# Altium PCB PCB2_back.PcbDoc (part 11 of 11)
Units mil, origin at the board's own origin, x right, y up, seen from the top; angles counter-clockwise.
Board outline 6299 x 3937 mil, 4 copper layers (TopLayer, GROUND, VCC, BottomLayer); 290 components, 470 nets, 2252 pads, 825 vias.
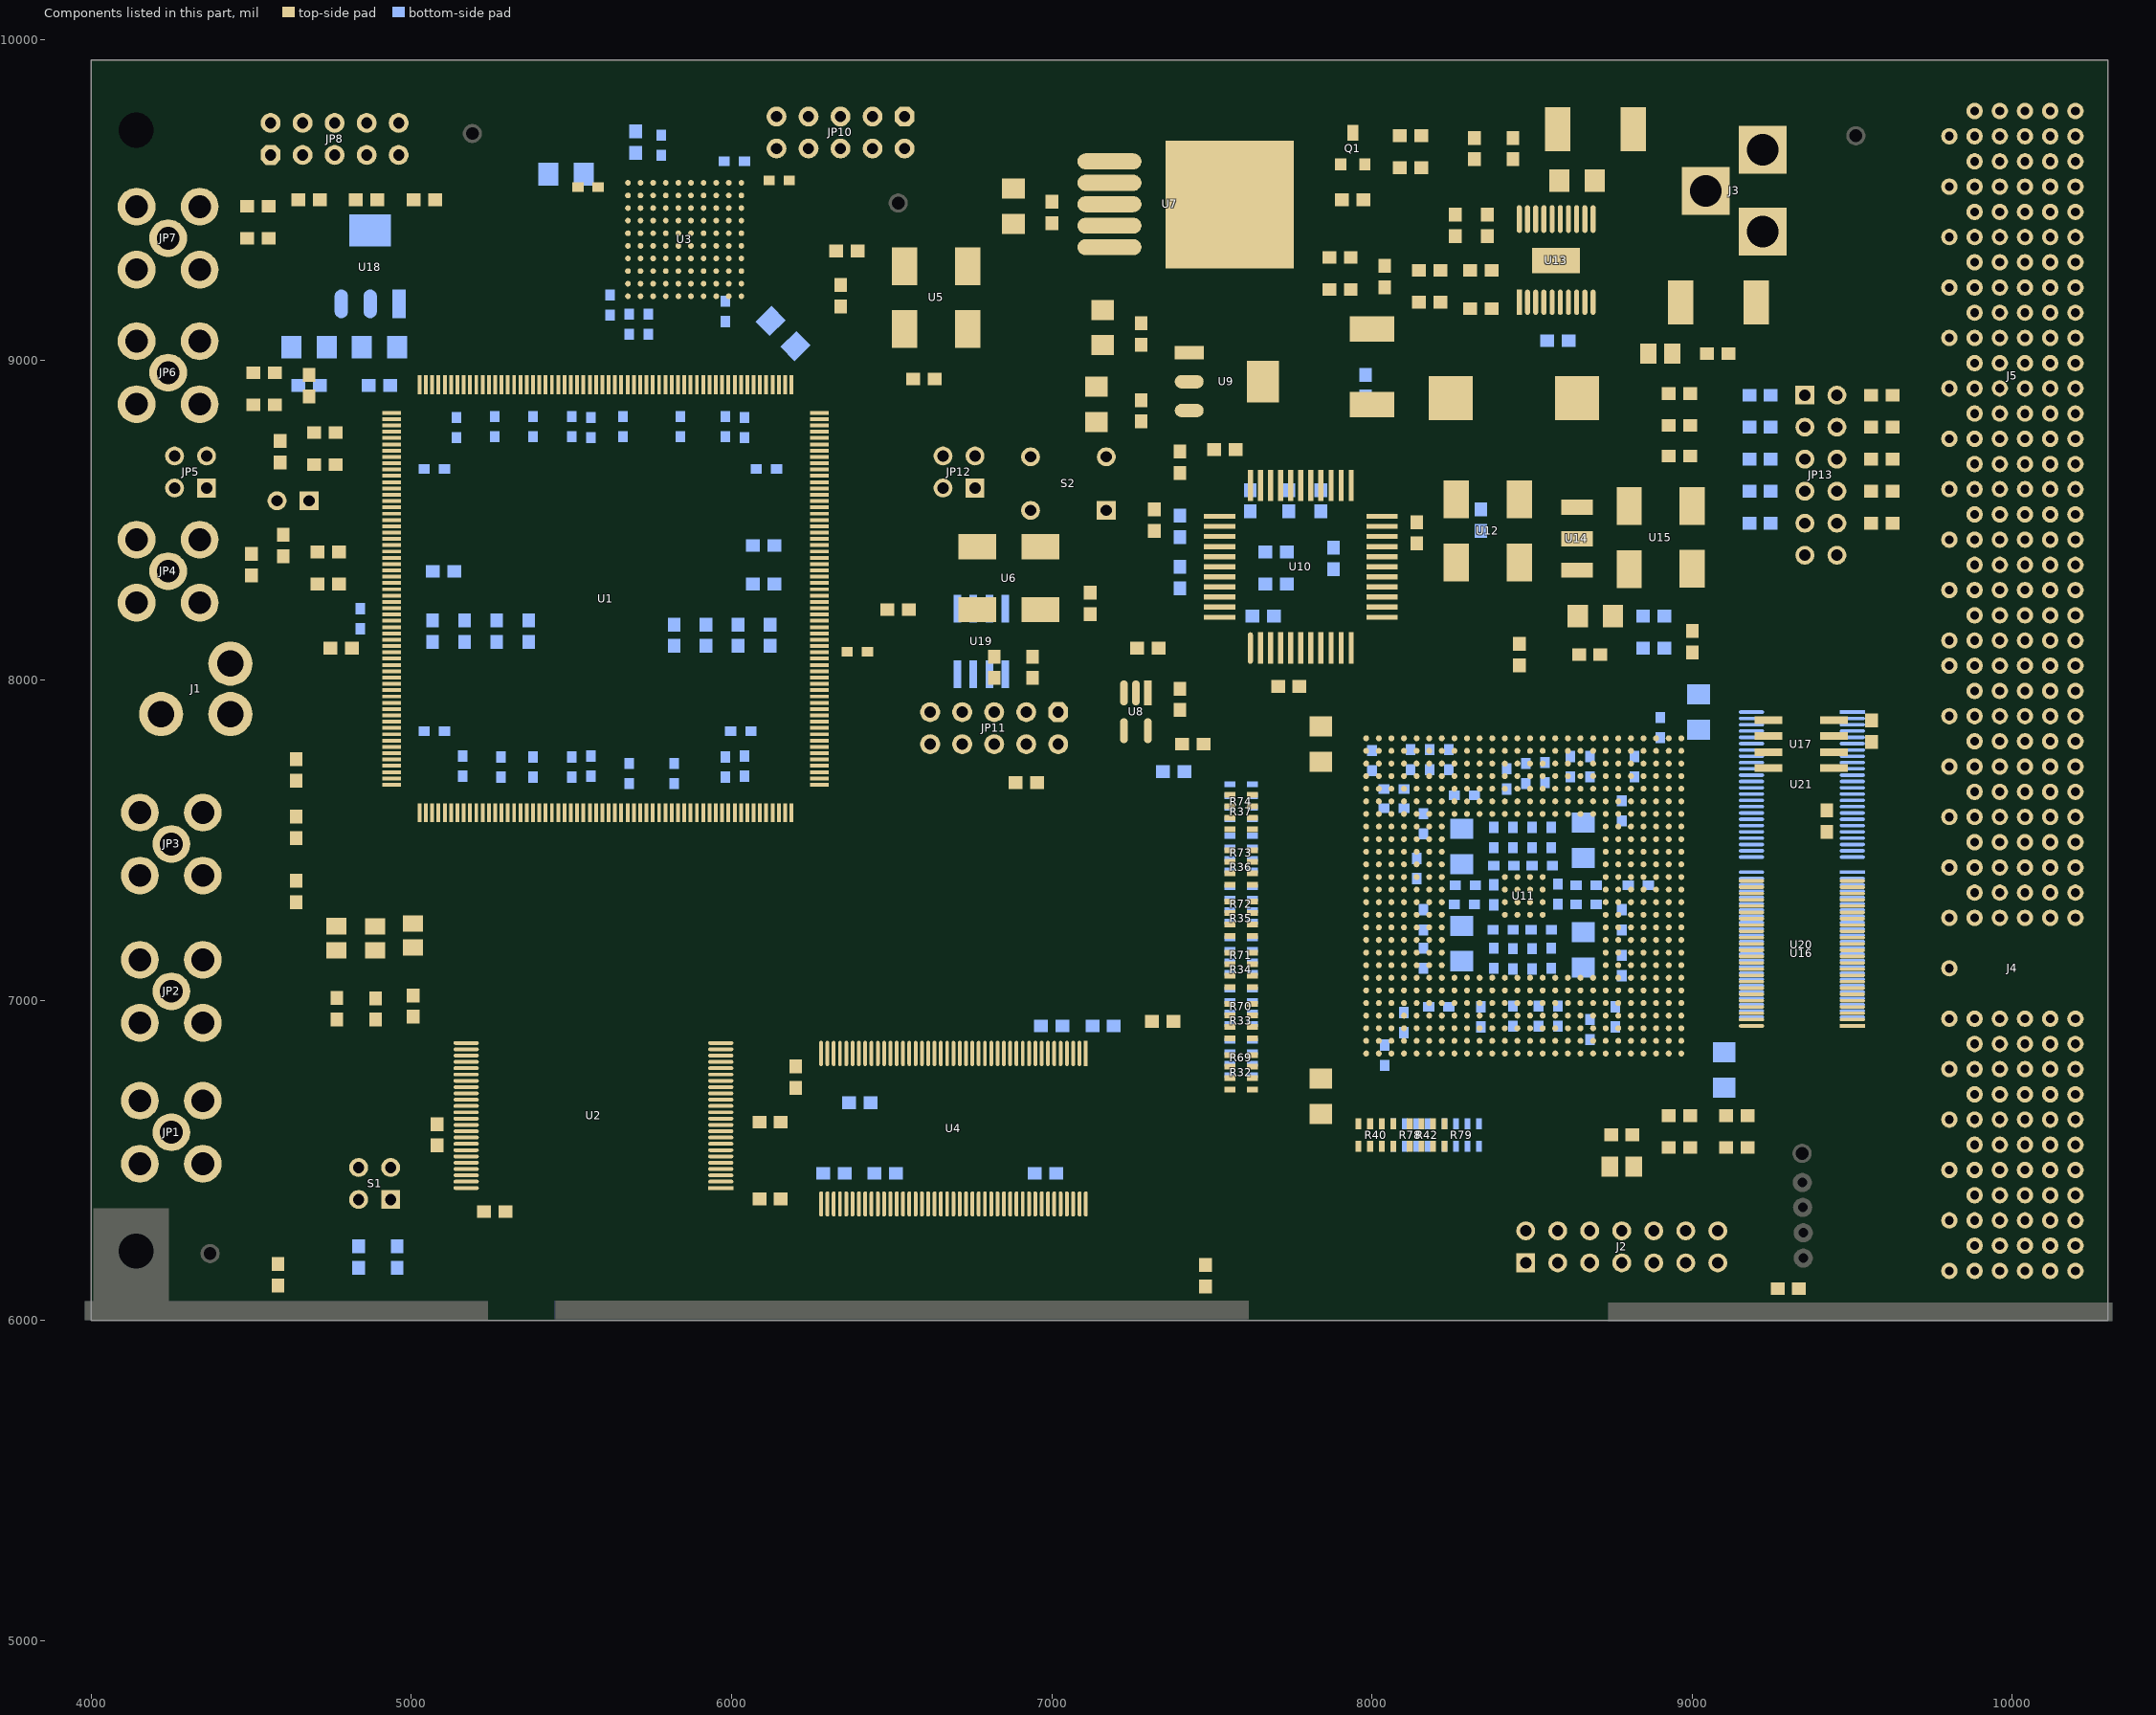
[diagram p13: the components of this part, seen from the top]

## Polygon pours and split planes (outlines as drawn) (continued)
V3.3 on VCC (split plane): 4238.02,6085.02 4238.02,6327.02 4086.01,6327.02 4086.01,9622.99 4239.02,9622.99 4239.02,9855.99 6698.98,9855.99 6698.98,9487 ccw(c6714,9487) 6713.9,9471.99 7318.98,9467.11 7318.98,9259.01 6927,9259.01 ccw(c6927,9244) 6911.98,9244 6911.98,9148.01 4868,9148.01 ccw(c4868,9133) 4852.98,9133 4852.98,8814 ccw(c4868,8814) 4868,8798.99 5021,8798.99 ccw(c5021,8814) 5036.02,8814 5036.02,8862.78 5130.22,8956.99 6764.75,8956.99 6416.78,8609.01 6145.02,8609.01 6145.02,8814 ccw(c6130,8814) 6130,8829.01 5162,8829.01 ccw(c5162,8814) 5146.98,8814 5146.98,8437 ccw(c5162,8437) 5151.4,8426.37 5151.38,8426.38 5255.98,8321.78 5255.98,7977.22 5180.38,7901.62 5180.4,7901.63 ccw(c5191,7891) 5175.98,7891 5175.98,7691 ccw(c5191,7691) 5191,7675.98 6018,7675.98 ccw(c6018,7691) 6033.02,7691 6033.02,7828.78 6541.22,8336.99 7395,8336.99 ccw(c7395,8352) 7405.63,8341.4 7405.62,8341.38 7633.22,8568.99 7798,8568.99 ccw(c7798,8584) 7809.19,8573.99 7991.98,8573.99 7991.98,7958 ccw(c8002,7958) 7994.92,7950.92 8256.92,7688.92 ccw(c8264,7696) 8264,7685.98 8388.85,7685.98 8421.99,7652.85 8421.99,7615.02 8259.15,7615.02 8223.08,7651.08 ccw(c8216,7644) 8216,7654.02 8154,7654.02 ccw(c8154,7644) 8143.98,7644 8143.98,7536 ccw(c8154,7536) 8146.92,7528.92 8181.98,7493.85 8181.98,7480.15 8156.92,7455.08 ccw(c8164,7448) 8153.98,7448 8153.98,7409 ccw(c8164,7409) 8156.92,7401.92 8187.98,7370.85 8187.98,7323 ccw(c8198,7323) 8190.92,7315.92 8217.99,7288.85 8217.99,7281.15 8152.92,7216.08 ccw(c8160,7209) 8149.98,7209 8149.98,7026 ccw(c8160,7026) 8152.92,7018.92 8172.92,6998.92 ccw(c8180,7006) 8180,6995.98 8195,6995.98 ccw(c8195,7006) 8202.08,6998.92 8246.15,7042.98 8663.85,7042.98 8702.92,7003.92 ccw(c8710,7011) 8710,7000.98 8782,7000.98 ccw(c8782,7011) 8789.08,7003.92 8812.08,7026.92 ccw(c8805,7034) 8815.01,7034 8815.01,7059 ccw(c8805,7059) 8812.08,7066.08 8745.01,7133.15 8745.01,7149.85 8790.08,7194.92 ccw(c8783,7202) 8793.01,7202 8793.01,7223 ccw(c8783,7223) 8790.08,7230.08 8762.08,7258.08 ccw(c8755,7251) 8755,7261.02 8735.01,7261.02 8735.01,7351.85 8779.08,7395.92 ccw(c8772,7403) 8782.01,7403 8782.01,7472 ccw(c8772,7472) 8779.08,7479.08 8763.01,7495.15 8763.01,7558.85 8796.08,7591.92 ccw(c8789,7599) 8799.01,7599 8799.01,7641 ccw(c8789,7641) 8789,7651.02 8677,7651.02 ccw(c8677,7641) 8666.99,7641 8666.99,7612.02 8536.01,7612.02 8536.01,7740 ccw(c8526,7740) 8533.08,7747.08 8267.01,8013.15 8267.01,8956.99 9220.99,8956.99 9220.99,8111 ccw(c9236,8111) 9236,8095.98 9679.99,8095.98 9679.99,7709.02 9343,7709.02 ccw(c9343,7694) 9327.99,7694 9327.99,6667 ccw(c9343,6667) 9343,6651.98 9679.99,6651.98 9679.99,6085.02
V3.3 on VCC (split plane): 4000,5979.98 cw(c4000,6000) 3979.99,6000 3979.99,9937 cw(c4000,9937) 4000,9957.01 10299,9957.01 cw(c10299,9937) 10319.01,9937 10319.01,6000 cw(c10299,6000) 10299,5979.98

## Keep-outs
KeepOutLayer:
  lines w8: 4064,6393 4065,9619 4240,9619 4240,9819 10090,9819 10240,9819 10240,9573 ; 9766,6119 10240,6119 ; 10240,6222 10240,6119 ; 10240,9619 10240,6319 10240,6119

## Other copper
TopLayer:
  rectangle net V5: 8601,9666 8664,9773
  rectangle net V5: 9197,9027 9286,9403
  rectangle net V1.4: 7884,8829 8225,8889
  rectangle net NetC102_2: 8590,8909 8693,9203
  rectangle net V5: 8566,9404 8613,9686
  rectangle net GND: 8638,9272 8691,9471
  rectangle net GND: 8459,9271 8507,9350
  rectangle net V3.3: 6776,9400 7139,9438
BottomLayer:
  text "P/N XXXXXX-XXX REV A" at 5320,10137 h40
GROUND (plane layer: these items are gaps in the copper):
  rectangle: 4014,9610 4245,9916
  rectangle: 4018,6007 4243,6324
  lines w20: 4313,8139 4313,7962 4313,7892 4313,7813 4311,7811 4470,7811 4551,7892 4639,7980 ; 4621,7962 4639,7980 ; 7436,8873 7436,8697 7410,8671 7310,8671 7310,8810 6225,8810 6187,8772 6187,8622 5979,8622 5693,8336 5693,8108 5565,7980 4639,7980
  lines w30: 4001,7714 4503,7714 4705,7916 5668,7916 5800,8048 5800,8331 5917.46,8448.46 5957,8488 6975,8488 7062,8575 7273,8575 7273,8505 7483,8505 7581,8603 7905,8603 7905,8778 ; 4001,8139 4564,8139 4670,8033 5532,8033 5640,8141 5640,8358 5956,8674 ; 7905,8745 7905,8873 6358,8873 6215,8872 6126,8782 6126,8674 ; 5956,8674 6126,8674 ; 5956,8674 6126,8674
  lines w50: 4001,6032 4001,9932 10292,9932 10292,6007 4001,6007 4001,6070
VCC (plane layer: these items are gaps in the copper):
  rectangle: 4075,9623 4239,9868
  rectangle: 4058,6067 4238,6327
  lines w20: 7798,8584 8002,8584 8002,7958 8264,7696 8393,7696 8432,7657 8432,7605 8255,7605 8216,7644 8154,7644 8154,7536 8192,7498 8192,7476 8164,7448 8164,7409 8198,7375 8198,7323 8228,7293 8228,7277 8160,7209 8160,7026 8180,7006 8195,7006 8242,7053 8668,7053 8710,7011 8782,7011 8805,7034 8805,7059 8735,7129 8735,7154 8783,7202 8783,7223 8755,7251 8725,7251 8725,7356 8772,7403 8772,7472 8753,7491 8753,7563 8789,7599 8789,7641 8677,7641 8677,7602 8526,7602 8526,7740 8257,8009 8257,8972
  lines w30: 6714,9906 6714,9487 7334,9482 ; 6810,8972 5124,8972 5021,8869 5021,8814 4868,8814 4868,9133 6927,9133 6927,9244 7334,9244 7334,9483 ; 7798,8972 7798,8911 7798,8584 7627,8584 7395,8352 6535,8352 6018,7835 6018,7691 5191,7691 5191,7891 5271,7971 5271,8328 5162,8437 5162,8814 6130,8814 6130,8803 6130,8594 6423,8594 6801,8972 6927,8972 8257,8972 9236,8972 9236,8111 9695,8111 9695,7694 ; 9647,7694 9695,7694 ; 9666,6667 9695,6667 ; 9695,6081 9695,6667 ; 9695,6667 9343,6667 9343,7694 9695,7694
  lines w100: 4036,6035 4036,9906 10268,9906 10268,6035 9695,6035 4036,6035

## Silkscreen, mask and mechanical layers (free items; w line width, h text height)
TopOverlay:
  circle w10: c4140,9717 r112.5
  lines w10: 4210,8647 4408,8647 ; 5392.59,10732.97 ccw(c5441,10772.5) 5392.71,10732.83
  text "GND" at 5246,9735 h40
  text "101_JTAG" at 6647,9703 h40
  text "GND" at 9581,9676 h40
  text "FPGA JTAG" at 5051,9560 h40
  text "3.3V" at 6553,9421 h40
  text "+" at 4351,9366 h40
  text "HOTLINK OUT" at 4452,9215 h40
  text "HOTLINK IN" at 4560,9119 h40
  text "+" at 4352,8945 h40
  text "1.4V" at 7930,8736 h40
  text "+" at 4161,8583 h40
  text "+" at 4420,8575 h40
  text "+" at 4487,8549 h40
  text "RESET" at 6884,8506 h40 r90
  text "test IO" at 6411,8476 h40
  text "+" at 4358,8325 h40
  text "50MHz" at 9064,8314 h40
  text "LVDS CLK" at 4436,8200 h40
  text "27MHz" at 8351,8169 h40
  text "CVBS OUT" at 4541,7909 h40
  text "FPGA AS MODE" at 6373,7678 h40
  text "+" at 4333,7474 h40
  text "LVDS IN3" at 4127,7233 h40
  text "IO175" at 5217,7138 h40 r90
  text "IO170" at 5140,7136 h40 r90
  text "IO176" at 5290,7133 h40 r90
  text "+" at 4343,7011 h40
  text "ECLKOUT1" at 7042,6990 h40
  text "LVDS IN2" at 4108,6785 h40
  text "LENDIAN" at 8659,6643 h40
  text "PCI_EN" at 9233,6625 h40
  text "EA22" at 4855,6594 h40 r90
  text "EA21" at 4960,6594 h40 r90
  text "+" at 4347,6573 h40
  text "GND" at 9394,6513 h40
  text "GP02" at 8538,6506 h40
  text "NMI" at 9077,6446 h40
  text "PXI_3.3V" at 9409,6415 h40
  text "PXI_VIO" at 9407,6333 h40
  text "LVDS IN1" at 4274,6332 h40
  text "PXI_-12V" at 9404,6253 h40
  text "DSP BOOT MODE" at 4677,6220 h40
  text "PXI_+12V" at 9400,6180 h40
  text "DSP JTAG" at 8041,6145 h40
  text "GND" at 4318,6120 h40
BottomOverlay:
  text "2.5V" at 4686,8817 h40 r180
  text "PCI66" at 9108,8179 h40
  text "EEAI" at 8850,7293 h40 r90
  text "BUAA PXI v1.0  byTX" at 6121,7245 h60
  text "2008.8.3" at 5227,7138 h40
TopSolder:
  lines w60: 4003,6033 10290,6031
BottomSolder:
  lines w60: 4003,6031 10290,6029
Mechanical1:
  the board outline again, w20
Mechanical4:
  lines w19.68: 10310.04,9162.4 10556.1,9162.4 ; 10311.02,7981.3 10425.2,7981.3 ; 10315.94,9712.6 10562.01,9712.6
  text ".Pcb_File_Name_No_Path" at 8099,10277 h40
  text ".Printout_Name" at 8099,10087 h40
  text "90.45" at 10635.83,9682.09 h40
  text "76.45" at 10638.78,9129.92 h40
  text "46.45" at 10452.76,7801.18 h40

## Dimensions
3980,6217 to 4000,6000 on Mechanical4
4140,5980 to 4000,6000 on Mechanical4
